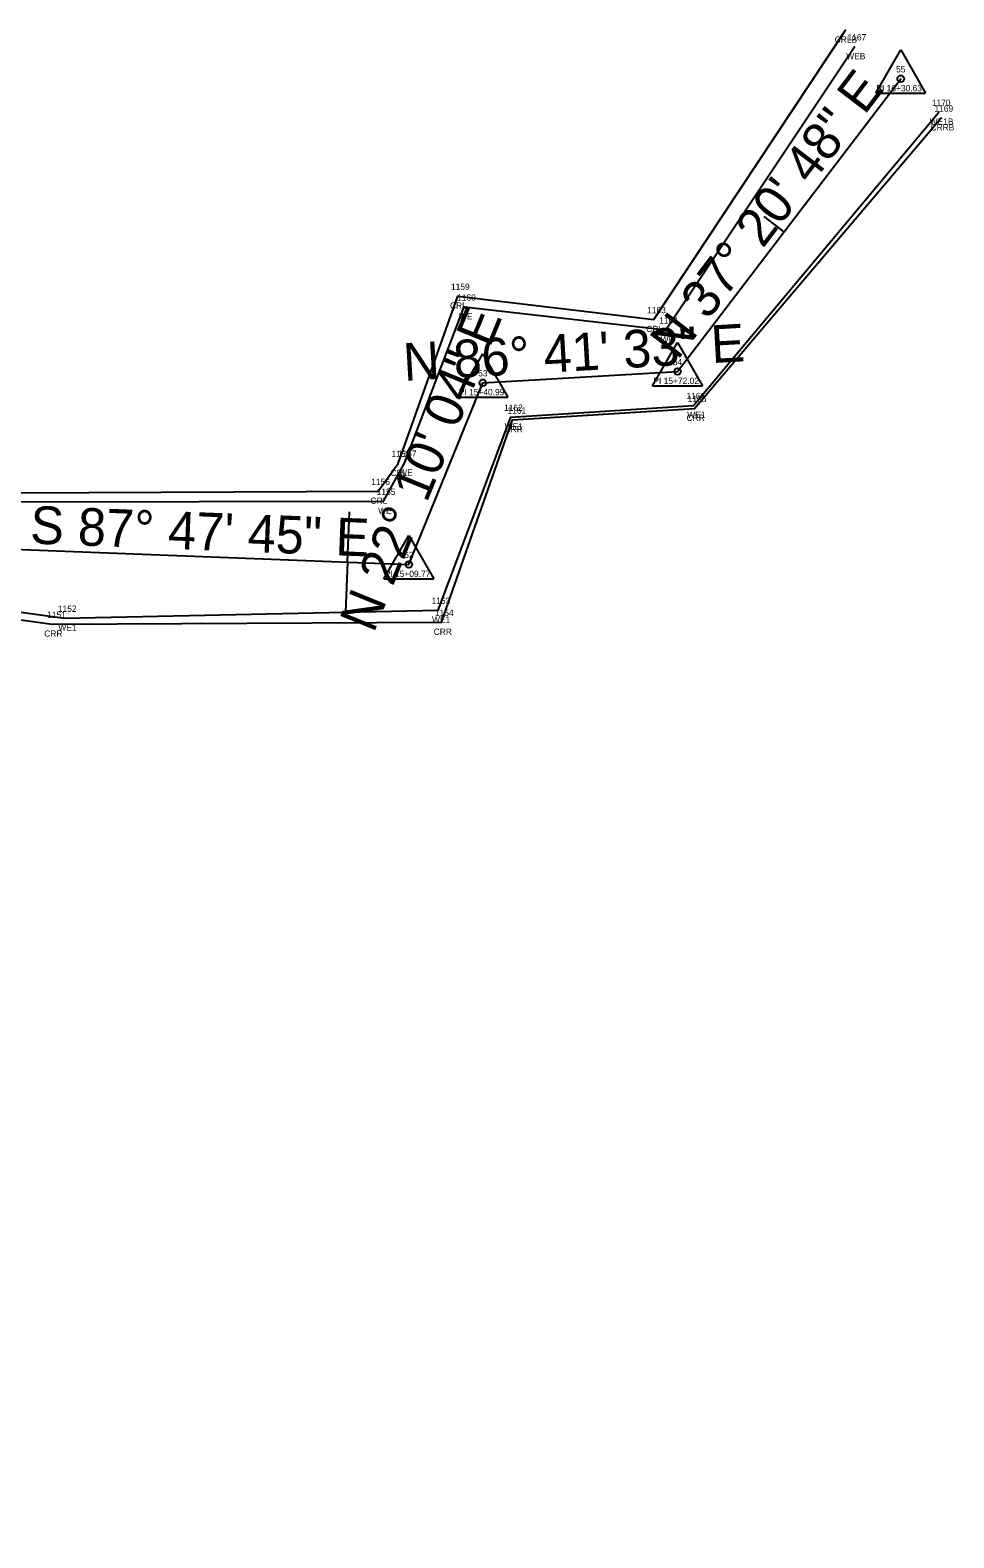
# Model space of a CAD drawing. Extents: x 2445178 to 2446205, y 790762 to 792372.
# Drawn here: x 2446057.5 to 2446204.5, y 791778.3 to 792018.2 of the extents above; entities that cross this region are included whole.
import ezdxf

# ---------------------------------------------------------------- set-up
doc = ezdxf.new("R2010")
doc.units = 0
for name, color, linetype in [('RD_EX_H2O', 7, 'Continuous'), ('RD_EX_H2O_txCode', 7, 'Continuous'), ('RD_HC_Cl', 7, 'Continuous'), ('RD_HC_Data', 7, 'Continuous'), ('RD_HC_Data_Tic', 7, 'Continuous'), ('RD_HC_txCode', 7, 'Continuous'), ('RD_SMD_Locator', 7, 'Continuous')]:
    doc.layers.add(name, color=color, linetype=linetype)

msp = doc.modelspace()

# ---------------------------------------------------------------- linework, layer by layer
at = {"layer": 'RD_EX_H2O'}
for points in [[(2445749.98, 791821.69), (2445784.5, 791816.33), (2445784.5, 791816.33), (2445826.97, 791831.85), (2445864.4, 791840.41), (2445865.35, 791848.28), (2445857.59, 791890.6), (2445862.25, 791903.98), (2445902.88, 791935.07), (2445928.13, 791937.54), (2445982.7, 791973.27), (2446006.36, 791974.66), (2446055.29, 791944.59), (2446112.86, 791944.82), (2446116.06, 791949.26), (2446125.53, 791975.87), (2446156.76, 791972.15), (2446187.24, 792018.21)], [(2445757.3, 791817.48), (2445784.85, 791815.29), (2445827.3, 791828.95), (2445865.88, 791838.48), (2445867.77, 791849.3), (2445858.86, 791890.39), (2445863.96, 791902.52), (2445903.58, 791933.29), (2445928.32, 791935.62), (2445983.75, 791971.59), (2446005.28, 791972.74), (2446055.03, 791943.12), (2446113.69, 791943.23), (2446117.06, 791949.31), (2446126.55, 791974.16), (2446158.67, 791970.49), (2446188.67, 792015.57)], [(2445746.88, 791778.25), (2445790.91, 791782.86), (2445846.87, 791809.11), (2445896.01, 791824.25), (2445877, 791883.78), (2445912.26, 791916.16), (2445942.78, 791927.77), (2445991.6, 791962.06), (2446003.69, 791956.06), (2446036.32, 791927.07), (2446060.96, 791923.67), (2446122.97, 791923.97), (2446134.24, 791956.18), (2446163.21, 791958.01), (2446202.51, 792004.24)], [(2445748.32, 791780.49), (2445788.24, 791788.44), (2445846, 791811.01), (2445891.85, 791826.96), (2445872.2, 791885.31), (2445911.58, 791917.24), (2445942.41, 791930.41), (2445989.95, 791963.2), (2446004.43, 791957.67), (2446037.13, 791928.19), (2446062.94, 791924.63), (2446122.42, 791925.89), (2446133.98, 791956.62), (2446163.05, 791958.48), (2446202.11, 792005.16)]]:
    msp.add_lwpolyline(points, dxfattribs=at)
at = {"layer": 'RD_HC_Cl'}
for p, q in [((2446160.5, 791963.89), (2446196.05, 792010.48)), ((2446129.52, 791962.1), (2446160.5, 791963.89)), ((2446117.74, 791933.18), (2446129.52, 791962.1)), ((2446051.43, 791935.74), (2446117.74, 791933.18))]:
    msp.add_line(p, q, dxfattribs=at)
at = {"layer": 'RD_HC_Data'}
for p, q in [((2446192.08, 792008.18), (2446196.05, 792015.06)), ((2446196.05, 792015.06), (2446200.02, 792008.18)), ((2446192.08, 792008.18), (2446200.02, 792008.18)), ((2446156.53, 791961.6), (2446160.5, 791968.48)), ((2446160.5, 791968.48), (2446164.47, 791961.6)), ((2446125.54, 791959.81), (2446129.52, 791966.69)), ((2446129.52, 791966.69), (2446133.49, 791959.81)), ((2446156.53, 791961.6), (2446164.47, 791961.6)), ((2446125.54, 791959.81), (2446133.49, 791959.81)), ((2446113.76, 791930.89), (2446117.74, 791937.77)), ((2446117.74, 791937.77), (2446121.71, 791930.89)), ((2446113.76, 791930.89), (2446121.71, 791930.89))]:
    msp.add_line(p, q, dxfattribs=at)
for centre in [(2446196.05, 792010.48), (2446160.5, 791963.89), (2446129.52, 791962.1), (2446117.74, 791933.18)]:
    msp.add_circle(centre, 0.529, dxfattribs=at)
at = {"layer": 'RD_HC_Data_Tic'}
for p, q in [((2446177.47, 791986.13), (2446174.29, 791988.56)), ((2446107.97, 791933.56), (2446108.28, 791941.55)), ((2446107.97, 791933.56), (2446107.67, 791925.57))]:
    msp.add_line(p, q, dxfattribs=at)
at = {"layer": 'RD_SMD_Locator'}
for centre in [(2446187.24, 792018.21), (2446188.67, 792015.57), (2446196.05, 792010.48), (2446202.11, 792005.16), (2446202.51, 792004.24), (2446125.53, 791975.87), (2446126.55, 791974.16), (2446156.76, 791972.15), (2446158.67, 791970.49), (2446160.5, 791963.89), (2446129.52, 791962.1), (2446163.05, 791958.48), (2446133.98, 791956.62), (2446134.24, 791956.18), (2446163.21, 791958.01), (2446116.06, 791949.26), (2446117.06, 791949.31), (2446112.86, 791944.82), (2446113.69, 791943.23), (2446117.74, 791933.18), (2446062.94, 791924.63), (2446122.42, 791925.89), (2446060.96, 791923.67), (2446122.97, 791923.97)]:
    msp.add_circle(centre, 0.001, dxfattribs=at)

# ---------------------------------------------------------------- texts
at = {"layer": 'RD_EX_H2O_txCode'}
for s, p in [('CRLB', (2446185.54, 792016.21)), ('1167', (2446187.59, 792016.57)), ('WEB', (2446187.38, 792013.57)), ('1170', (2446201.01, 792006.16)), ('1169', (2446201.43, 792005.24)), ('WE1B', (2446200.65, 792003.16)), ('CRRB', (2446200.79, 792002.24)), ('1159', (2446124.46, 791976.87)), ('CRL', (2446124.3, 791973.87)), ('1160', (2446125.43, 791975.16)), ('WE', (2446125.72, 791972.16)), ('1163', (2446155.68, 791973.15)), ('1164', (2446157.58, 791971.49)), ('CRL', (2446155.53, 791970.15)), ('WE', (2446157.83, 791968.49)), ('1166', (2446161.94, 791959.48)), ('1162', (2446132.9, 791957.62)), ('1161', (2446133.44, 791957.18)), ('1165', (2446162.13, 791959.01)), ('CRR', (2446161.96, 791956.01)), ('WE1', (2446162.06, 791956.48)), ('WE1', (2446133, 791954.62)), ('CRR', (2446132.99, 791954.18)), ('1158', (2446114.99, 791950.26)), ('1157', (2446115.99, 791950.31)), ('1156', (2446111.77, 791945.82)), ('CRL', (2446114.83, 791947.26)), ('WE', (2446116.22, 791947.31)), ('CRL', (2446111.63, 791942.82)), ('1155', (2446112.63, 791944.23)), ('WE', (2446112.86, 791941.23)), ('1153', (2446121.36, 791926.89)), ('1151', (2446060.18, 791924.67)), ('1152', (2446061.88, 791925.63)), ('WE1', (2446121.44, 791923.89)), ('1154', (2446121.9, 791924.97)), ('CRR', (2446059.71, 791921.67)), ('WE1', (2446061.96, 791922.63)), ('CRR', (2446121.71, 791921.97))]:
    msp.add_text(s, height=1, dxfattribs=at).set_placement(p)
at = {"layer": 'RD_HC_Data'}
for s, rotation, p in [('N 37%%d 20\' 48" E', 52.6534, (2446160.5, 791965.55)), ('N 22%%d 10\' 04" E', 67.8323, (2446112.14, 791922.11)), ('N 86%%d 41\' 33" E', 3.3074, (2446117.02, 791962.38)), ('S 87%%d 47\' 45" E', 357.7958, (2446057.4, 791936.51))]:
    msp.add_text(s, height=6, rotation=rotation, dxfattribs=at).set_placement(p)
at = {"layer": 'RD_HC_txCode'}
for s, p in [('55', (2446195.32, 792011.48)), ('PI 16+30.63', (2446192.18, 792008.48)), ('54', (2446159.76, 791964.89)), ('53', (2446128.78, 791963.1)), ('PI 15+72.02', (2446156.68, 791961.89)), ('PI 15+40.99', (2446125.7, 791960.1)), ('52', (2446117, 791934.18)), ('PI 15+09.77', (2446113.92, 791931.18))]:
    msp.add_text(s, height=1, dxfattribs=at).set_placement(p)

doc.saveas('drawing.dxf')
